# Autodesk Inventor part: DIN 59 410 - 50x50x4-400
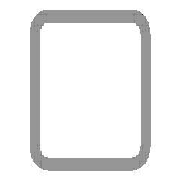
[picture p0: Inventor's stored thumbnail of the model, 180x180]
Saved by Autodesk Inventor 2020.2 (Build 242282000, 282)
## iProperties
Manager: www.cadconsulting.pl
Company: Fabian Stasiak CAD Consulting
Created: 2015-01
Part Number: DIN 59 410 - 50x50x4-400
Material: Stal, miękka
Description: Rurki stalowe o przekroju kwadratowym formowane na gorąco
Document SubType Name: Modellieren
Standard: DIN
Designer: F.Stasiak
Standards Organization: DIN
Language: pl-PL
Size Designation: 50x50x4
Categories: <MemberInstance><Categories><Category DisplayName="Kształtowniki konstrukcyjne" InternalName="089c4875-fa83-4c05-b084-43b9cc11f5ed" Mnemonic="GRDR"><CategoryPar
Stock Number: 50x50x4
Density: 7.85 g/cm^3
Appearance: Częściowo polerowana
Mass: 2181.66 g
Surface Area: 1403.49 cm^2
Volume: 277.919 cm^3
Catalog Web Link: www.expertbooks.pl
_CCFamilyMember: 40
_CCFamilyDisplayName: DIN 59410 (Kwadrat) - Rurki stalowe o przekroju kwadratowym formowane na gorąco
_FrameMemberDoc: Frame Member File
_Version: 15.0.0
_GetPNFromCC: 1
G_W: 50,000 mm
G_H: 50,000 mm
+C55E4939-7475-41BA-A921-1669EB8DC7C4+CUTDETAIL1: Wytnij
+C76EC201-503E-4935-BA63-CB7D056E2BCD+CUTDETAIL2: Wytnij
G_L: 400,000 mm
IsCustomPart: 1
Author: F.Stasiak
Subject: Zbiór ćwiczeń. Autodesk Inventor 2020. Kurs Professional
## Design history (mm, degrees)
node "Płaszczyzna początkowa"
node "Płaszczyzna końcowa"
sketch "Szkic"
  geometry: L1 (-17, 25)-(17, 25); L2 (25, 17)-(25, -17); L3 (17, -25)-(-17, -25); L4 (-25, -17)-(-25, 17); L5 (-37.32, 0)-(37.32, 0) reference; L6 (0, -37.32)-(0, 37.32) reference; L7 (-17, 21)-(17, 21); L8 (21, 17)-(21, -17); L9 (17, -21)-(-17, -21); L10 (-21, -17)-(-21, 17); A1 r 8 centre (-17, 17) between (-17, 25) and (-25, 17); A2 r 8 centre (17, 17) between (25, 17) and (17, 25); A3 r 8 centre (17, -17) between (17, -25) and (25, -17); A4 r 8 centre (-17, -17) between (-25, -17) and (-17, -25); A5 r 4 centre (-17, 17) between (-17, 21) and (-21, 17); A6 r 4 centre (17, 17) between (21, 17) and (17, 21); A7 r 4 centre (17, -17) between (17, -21) and (21, -17); A8 r 4 centre (-17, -17) between (-21, -17) and (-17, -21); 3 further points
  constraints: 16 end point, 16 point on circle, 8 centre point, 8 tangent, 6 point on line, 4 parallel, 3 equal radius, 3 perpendicular, 1 horizontal, 7 other
  dimensions: "b" = 50 distance of point (-25, 25) point (25, 25); "msp_r" = 8 radius of A1 (= 2 x ParT); "d8" = 25 distance between parallel lines of L4 L6 (= d9); "d9" = 25 distance between parallel lines of L3 L5 (= 0.5 x b); "d10" = 4 distance between parallel lines of L3 L9 (= ParT)
extrude "Bryła" new body sketch "Szkic" taper "d4" = 0 deg; stored distance "NLG" = 10
node "Driven Length"
  sketch "Sketch2"
    geometry: L1 (0, 0)-(10, 0) reference
    constraints: 2 end point, 1 horizontal
  workplane "Work Plane3"
  sketch "Sketch3"
    geometry: L1 (-2, 25)-(12, 25) reference; L2 (-2, 425)-(12, 425) reference
    dimensions: "d14" = 400 distance between parallel lines of L1 L2 (derived)
node "Płaszczyzna konstrukcyjna4"
feature "Podział1"
node "Płaszczyzna konstrukcyjna5"
feature "Podział2"
body "Solid1"
other parameters: "ParT" = 4, "G_OFFSET_START" = -25 [user parameter; used in 1 equation term], "G_OFFSET_END" = -25 [user parameter; used in 1 equation term], "d11" = 25 (= -G_OFFSET_START), "d12" = 425 (= G_OFFSET_END + B_L), "G_L" = 400 (= d14) [user parameter], "d13" = 90 deg
